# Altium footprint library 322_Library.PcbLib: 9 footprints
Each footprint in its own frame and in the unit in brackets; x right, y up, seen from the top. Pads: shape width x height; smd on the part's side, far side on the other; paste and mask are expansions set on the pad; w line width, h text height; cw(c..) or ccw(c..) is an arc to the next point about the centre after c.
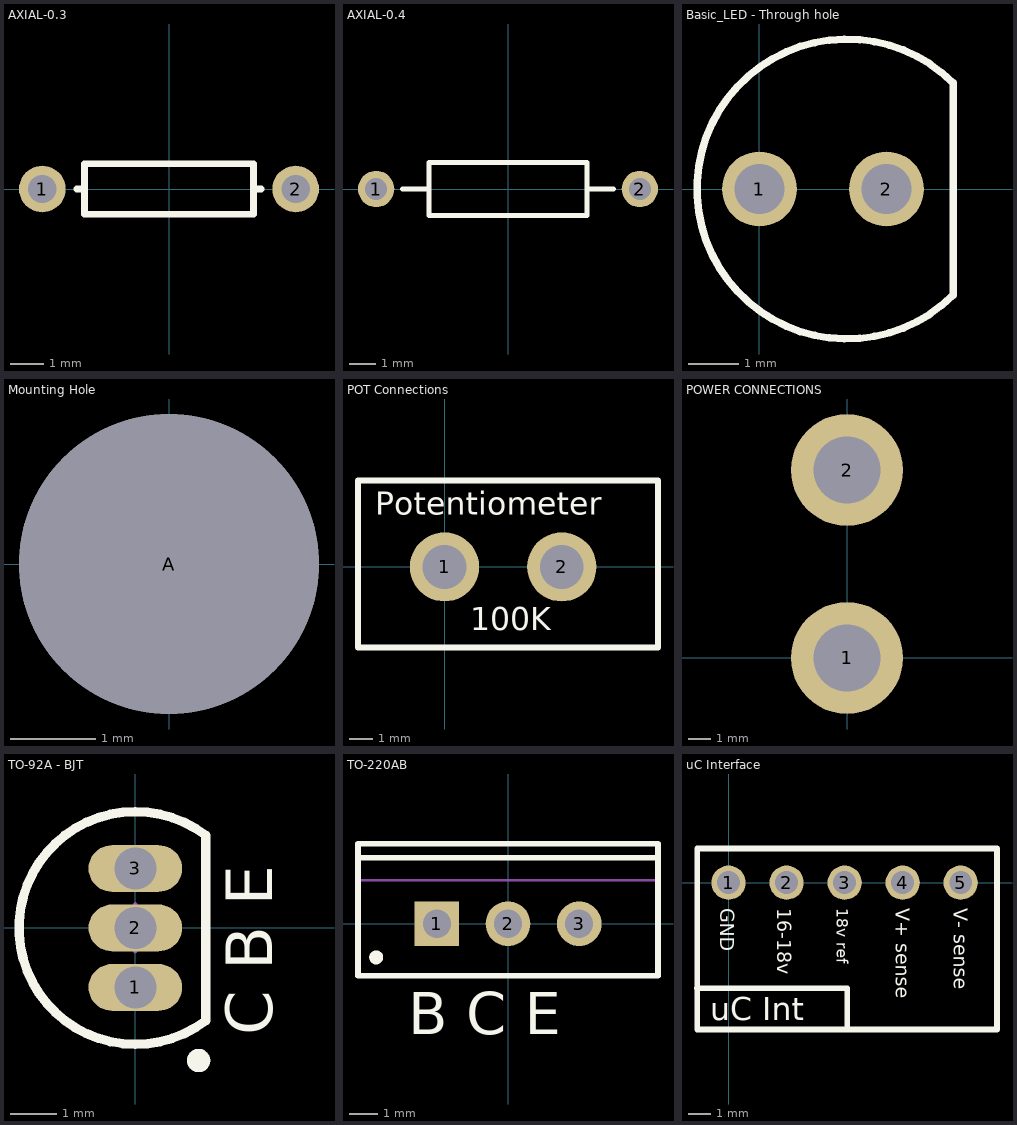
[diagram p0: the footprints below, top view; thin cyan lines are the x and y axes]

## AXIAL-0.3 [mm] "Axial Device, Thru-Hole; 2 Leads; 0.3 in Pin Spacing"
height 1.524
pads (2):
  round 1.4 hole 0.85: 1(-3.81,0) 2(3.81,0)
Top Overlay:
  lines w0.2: -2.769,0 -2.54,0 ; 2.769,0 2.54,0 ; 2.54,0 2.54,-0.762 -2.54,-0.762 -2.54,0.762 2.54,0.762 2.54,0

## AXIAL-0.4 [mm] "Axial Device, Thru-Hole; 2 Leads; 0.4 in Pin Spacing"
height 2.032
pads (2):
  round 1.4 hole 0.85: 1(-5.08,0) 2(5.08,0)
Top Overlay:
  lines w0.2: -4.064,0 -3.048,0 ; 3.048,0 4.064,0 ; -3.048,-1.016 -3.048,1.016 3.048,1.016 3.048,-1.016 -3.048,-1.016

## Basic_LED - Through hole [mm]
pads (2):
  round 1.5 hole 1: 1(0,0) 2(2.54,0)
Top Overlay:
  lines w0.15: 3.871,-2.121 cw(c1.75,0) 3.871,2.121 3.871,-2.121

## Mounting Hole [mm]
pads (1):
  round 3.5 hole 3.5: A(0,0)

## POT Connections [mm] "Connection for an external potentiometer"
pads (2):
  round 3 hole 1.9: 1(0,0) 2(5.08,0)
Top Overlay:
  lines w0.254: -3.75,-3.5 -3.75,3.75 9.25,3.75 9.25,-3.5 -3.75,-3.5
  text "Potentiometer" at -3,2.25 h1
  text "100K" at 1.125,-2.75 h1

## POWER CONNECTIONS [mm]
pads (2):
  round 5 hole 3: 1(0,0) 2(0,8.375)

## TO-92A - BJT [mm] "TO, Flat Index; 3 In-Line, Axial Leads; Body Dia. 4.5mm; Leads 0.51 x 0.48 mm (max)"
height 6.86
pads (3):
  oval 2x1 hole 0.9: 1(0,-1.27) 2(0,0) 3(0,1.27)
Top Overlay:
  circle w0.25: c1.35,-2.83 r0.125
  lines w0.2: 1.5,-1.98 cw(c0,0) 1.5,1.98 1.5,-1.98
  text "C B E" at 2.921,-2.286 h1
Mechanical 13:
  lines w0.1: 1.5,-1.98 cw(c0,0) 1.5,1.98 1.5,-1.98
Mechanical 15:
  lines w0.1: -0.5,0 0.5,0 ; 0,-0.5 0,0.5
3D body: height 6.86, standoff 2.2, extent -2.485,-2.495 1.501,2.495

## TO-220AB [mm] "TO, Thru-Hole, Vertical, Heatsink Mounted; 3 In-Line Leads; Pitch 2.54 mm"
height 19.3
pads (3):
  rect 1.6x1.6 hole 1: 1(-2.54,0)
  round 1.6 hole 1: 2(0,0) 3(2.54,0)
Top Overlay:
  circle w0.25: c-4.7,-1.2 r0.125
  lines w0.2: -5.35,2.35 5.35,2.35 ; -5.35,-1.85 5.35,-1.85 5.35,2.85 -5.35,2.85 -5.35,-1.85
  text "B C E" at -3.556,-3.937 h1.5
Mechanical 13:
  lines w0.1: -5.35,1.55 5.35,1.55 ; -5.35,-1.85 -5.35,2.85 5.35,2.85 5.35,-1.85 -5.35,-1.85
Mechanical 15:
  lines w0.1: -0.5,0 0.5,0 ; 0,-0.5 0,0.5
3D body: height 19.3, standoff 12.9, extent -5.349,1.551 5.349,2.849
3D body: height 12.9, standoff 4, extent -5.4,-1.9 5.4,2.9

## uC Interface [mm] "uC Interface"
pads (5):
  round 1.5 hole 1: 1(0,0) 2(2.54,0) 3(5.08,0) 4(7.62,0) 5(10.16,0)
Top Overlay:
  lines w0.254: -1.383,-4.625 5.191,-4.625 5.191,-6.429 ; -1.375,-6.433 -1.375,1.5 11.75,1.5 11.75,-6.433 -1.375,-6.433
  text "V- sense" at 9.86,-1.125 h0.6
  text "V+ sense" at 7.32,-1.125 h0.6
  text "18v ref" at 4.73,-1.125 h0.5
  text "16-18v" at 2.125,-1.125 h0.6
  text "GND" at -0.375,-1.125 h0.6
  text "uC Int" at -0.806,-6.02 h1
